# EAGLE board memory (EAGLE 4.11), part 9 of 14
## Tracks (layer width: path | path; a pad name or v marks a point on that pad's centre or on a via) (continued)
MB04  (via drill 0.61) (continued)
  Route2 0.254: v274.95,203.2 279.4,207.64 291.46,207.64 292.1,207.01 309.25,207.01 309.88,207.64 315.6,207.64 321.31,201.93 327.66,201.93 328.3,201.29 329.56,201.29 334.01,205.74 379.1,205.74 381,207.64 383.54,207.64 384.18,207.01 386.71,207.01 v387.99,208.28 | v462.28,256.54 466.73,252.09 474.35,252.09 474.35,248.28 C03.K2
  Route3 0.254: v274.95,203.2 276.23,201.93 276.23,188.59 279.4,185.42 279.4,182.88 280.67,181.61 D18.J2 | v387.99,208.28 395.61,215.9 398.14,215.9 398.14,218.44 v398.78,219.07 | B37.P2 43.18,302.26 43.81,302.9 43.81,306.71 44.45,307.34 44.45,326.39 53.98,335.92 53.98,384.81 87.63,418.47 151.76,418.47 156.84,413.39 189.23,413.39 190.5,412.12 200.03,412.12 200.66,412.75 236.85,412.75 236.85,410.21 239.4,407.67 248.28,407.67 259.71,419.1 352.43,419.1 352.43,387.99 372.75,367.67 372.75,365.76 A11.S2 | v440.06,265.43 438.15,267.34 438.15,324.49 439.42,325.75 439.42,328.3 438.15,329.56 438.15,335.92 433.07,341 v433.07,343.54
  Bottom 0.254: v439.42,170.18 434.98,170.18 434.98,163.83 433.7,162.56 D06.R2 | v474.35,224.16 466.73,216.53 437.51,216.53 v436.88,217.17 426.72,217.17 425.45,218.44 424.81,217.81 419.74,217.81 416.56,220.98 414.02,220.98 413.38,220.34 404.5,220.34 403.86,220.98 400.69,220.98 v398.78,219.07 | v462.28,256.54 460.38,258.44 453.39,258.44 452.75,259.08 448.31,259.08 441.96,265.43 v440.06,265.43 | v433.07,343.54 432.44,342.9 409.57,342.9 404.5,347.98 399.42,347.98 398.78,347.35 377.19,347.35 374.65,349.89 370.84,349.89 v370.2,349.25 | v368.3,363.86 368.94,364.49 372.75,364.49 A11.S2
MB05  (via drill 0.61)
  Top 0.254: 330.2,95.88 v331.47,97.16 | 330.2,95.88 330.2,80.64 332.11,78.74 332.11,65.41 333.38,64.13 v333.38,23.49 | v328.3,107.95 330.2,106.04 330.2,95.88 | v496.57,222.88 495.94,222.25 495.94,220.34 495.3,219.71 495.3,167 496.57,165.73 v496.57,164.47 | v502.92,137.16 504.82,135.25 v504.82,60.33 | v445.13,9.52 441.96,9.52 435.61,3.17 412.75,3.17 412.75,20.32 411.48,21.59 F08.S2 | v246.38,220.34 245.75,219.71 v245.75,208.91
  Route2 0.254: v484.5,228.6 485.77,228.6 485.77,251.46 478.15,259.08 475.62,259.08 474.98,259.72 C03.E2 | v246.38,220.34 247.65,220.34 247.65,229.23 247.01,229.87 243.21,229.87 240.03,226.69 239.4,226.69 238.76,227.33 229.87,227.33 219.07,216.53 173.35,216.53 172.09,217.81 165.74,217.81 162.56,220.98 160.02,220.98 156.21,217.17 114.94,217.17 92.71,239.39 88.9,239.39 88.9,248.92 59.69,278.13 54.61,278.13 51.44,281.31 43.18,281.31 43.18,288.29 B37.U2 | v263.52,160.66 273.69,160.66 274.32,160.02 275.59,160.02 277.5,161.92 280.67,161.92 D18.R2
  Route3 0.254: v43.18,292.1 43.18,289.56 B37.U2 | v27.3,302.26 25.4,304.17 25.4,346.08 15.88,355.6 15.88,388.62 17.14,389.89 A39.H2 | v287.65,111.12 285.75,113.03 285.75,120.02 282.57,123.19 282.57,135.25 281.31,136.53 281.31,144.78 282.57,146.05 282.57,160.02 281.31,161.29 D18.R2 | v245.75,208.91 241.3,204.47 241.3,173.99 v242.57,172.72
  Bottom 0.254: v43.18,292.1 45.09,294 45.09,297.18 36.83,297.18 33.66,300.36 29.21,300.36 v27.3,302.26 | v331.47,97.16 338.45,97.16 339.09,96.52 346.07,96.52 347.35,97.79 E13.P2 | v333.38,23.49 340.36,23.49 341,24.13 349.88,24.13 350.52,23.49 353.06,23.49 353.69,24.13 360.05,24.13 360.68,23.49 365.76,23.49 366.39,24.13 375.29,24.13 375.92,23.49 378.46,23.49 379.1,24.13 380.37,24.13 381,23.49 391.16,23.49 391.8,24.13 400.69,24.13 404.5,20.32 409.57,20.32 410.85,21.59 F08.S2 | v287.65,111.12 289.56,109.22 299.08,109.22 299.72,109.85 302.26,109.85 302.89,109.22 311.79,109.22 312.42,109.85 314.96,109.85 315.6,109.22 324.49,109.22 325.12,109.85 326.39,109.85 v328.3,107.95 | v484.5,228.6 485.77,227.33 492.12,227.33 v496.57,222.88 | v496.57,164.47 501.65,159.38 501.65,137.16 v502.92,137.16 | v504.82,60.33 504.82,27.3 494.67,27.3 476.88,9.52 v445.13,9.52 | v242.57,172.72 247.01,172.72 250.82,168.91 250.82,163.83 251.46,163.83 257.81,157.48 260.35,157.48 v263.52,160.66
MB06  (via drill 0.61)
  Top 0.254: v190.5,377.19 190.5,388.62 196.85,394.97 196.85,407.04 205.1,415.29 v252.09,415.29 | v294,414.02 298.45,414.02 298.45,392.43 297.18,391.16 A17.H2 | v238.12,217.81 v238.12,210.19 | v194.31,223.52 193.68,224.16 193.68,299.72 v191.77,301.62 | v179.71,325.75 179.71,329.56 B26.D2 | v426.72,59.05 428.62,60.96 428.62,71.12 425.45,74.29 425.45,78.74 428.62,81.91 428.62,86.36 v430.53,88.27 | v461.64,119.38 462.92,120.65 462.92,122.55 463.55,123.19 463.55,144.78 v464.82,146.05 | v459.11,209.55 459.74,210.19 459.74,217.81 460.38,218.44 460.38,221.61 v458.47,223.52
  Route2 0.254: v430.53,88.27 v461.64,119.38 | v464.82,146.05 488.95,170.18 488.95,195.58 486.41,195.58 478.79,203.2 478.79,209.55 v459.11,209.55 | v458.47,223.52 450.85,231.14 450.85,236.85 445.13,236.85 444.5,237.49 444.5,242.57 443.87,242.57 440.06,246.38 439.42,246.38 438.15,247.65 438.15,248.92 v427.36,259.72
  Route3 0.254: v338.45,53.98 336.55,52.07 336.55,46.99 335.92,46.36 335.92,44.45 332.11,44.45 F14.J2 | v190.5,377.19 186.69,373.38 186.69,371.48 184.15,368.94 184.15,357.5 177.8,351.16 177.8,335.92 178.44,335.28 178.44,331.47 179.07,330.84 B26.D2 | v277.5,209.55 277.5,207.01 279.4,205.1 279.4,199.39 280.04,198.75 280.04,194.94 280.67,194.31 D18.D2 | v191.77,301.62 187.32,306.07 187.32,324.49 v186.06,325.75 | v403.23,408.94 415.93,396.24 415.93,313.69 416.56,313.06 416.56,311.15 422.27,305.44 422.27,294.64 422.91,294 422.91,290.2 423.55,289.56 B07.U2 424.18,288.29 424.18,280.04 425.45,278.77 425.45,261.62 v427.36,259.72 | v319.4,412.12 314.32,417.2 294,417.2 v294,414.02
  Bottom 0.254: v338.45,53.98 340.36,55.88 342.26,55.88 342.9,55.25 353.06,55.25 353.69,55.88 360.05,55.88 363.22,59.05 364.49,59.05 368.3,55.25 378.46,55.25 379.1,55.88 387.99,55.88 388.62,55.25 391.16,55.25 391.8,55.88 396.88,55.88 398.14,54.61 F09.E2 398.78,54.61 399.42,55.25 403.86,55.25 407.67,59.05 416.56,59.05 417.19,58.42 426.08,58.42 v426.72,59.05 | v252.09,415.29 252.73,414.66 269.24,414.66 269.88,414.02 v294,414.02 | v277.5,209.55 276.86,208.91 265.43,208.91 263.52,210.82 238.76,210.82 v238.12,210.19 | v238.12,217.81 238.12,220.98 227.97,220.98 227.33,220.34 224.79,220.34 220.98,224.16 212.09,224.16 211.46,223.52 202.56,223.52 201.93,224.16 199.39,224.16 198.75,223.52 v194.31,223.52 | v179.71,325.75 v186.06,325.75 | v403.23,408.94 403.23,412.75 398.78,412.75 398.14,413.39 376.56,413.39 375.92,412.75 364.49,412.75 363.86,413.39 331.47,413.39 330.2,412.12 v319.4,412.12
MB07  (via drill 0.61)
  Top 0.254: C07.L2 421,245.11 421,247.65 422.91,249.56 422.91,252.73 422.27,253.36 422.27,299.72 423.55,300.99 B07.P2 | v442.6,239.39 441.32,238.12 v441.32,219.07 v441.32,207.64 | v346.07,111.76 v346.07,92.71 | v346.71,115.57 346.07,116.2 v346.07,143.51 346.07,153.67 v347.98,155.57 | v296.55,144.14 295.27,145.41 v295.27,168.28 | v284.48,168.91 281.31,172.09 281.31,173.99 D18.L2 | v390.52,190.5 v390.52,208.28
  Route2 0.254: v346.07,92.71 344.81,92.71 344.81,89.53 E13.T2 | v346.07,111.76 346.07,109.85 348.62,109.85 349.25,110.49 349.25,115.57 v346.71,115.57 | v372.75,187.32 364.49,179.07 358.77,179.07 355.6,175.89 355.6,160.66 353.06,160.66 v347.98,155.57
  Bottom 0.254: v441.32,219.07 442.6,219.07 445.77,222.25 448.94,222.25 C05.U2 | v442.6,239.39 438.79,243.2 427.99,243.2 427.36,242.57 422.27,242.57 421,243.84 C07.L2 | v346.07,143.51 345.44,144.14 318.77,144.14 317.5,142.88 314.96,142.88 313.06,144.78 297.18,144.78 v296.55,144.14 | v295.27,168.28 295.27,169.54 288.29,169.54 287.65,170.18 285.75,170.18 v284.48,168.91 | v441.32,207.64 431.17,207.64 429.89,208.91 391.16,208.91 v390.52,208.28 | v390.52,190.5 389.25,189.23 380.37,189.23 379.73,188.59 377.19,188.59 376.56,189.23 374.65,189.23 v372.75,187.32
MB08  (via drill 0.61)
  Top 0.254: v283.85,150.5 284.48,149.86 284.48,138.43 285.75,137.16 285.75,124.46 v287.65,122.55 | v290.19,83.82 290.83,83.18 290.83,73.66 292.1,72.39 292.1,59.69 293.37,58.42 296.55,58.42 296.55,54.61 F17.E2 | v361.31,231.78 365.12,227.97 v365.12,220.34 | v425.45,217.17 425.45,222.88 424.81,223.52 424.81,227.33 424.18,227.97 C07.S2 424.18,229.23 424.18,233.04 425.45,234.31 425.45,281.94 424.81,282.58 424.81,287.66 425.45,288.29 425.45,312.42 424.18,313.69 B07.K2 423.55,314.96 423.55,318.77 422.27,320.04 422.27,340.36 423.55,341.63 v423.55,356.87 | v36.2,373.38 39.37,376.56 44.45,376.56 44.45,394.34 67.31,417.2 v71.12,417.2 | v153.03,418.47 154.31,417.2 v154.31,414.66 | v393.7,416.56 400.05,410.21 v400.05,370.84
  Route2 0.254: v283.85,150.5 281.31,150.5 281.31,154.94 D18.T2 | v350.52,241.3 354.33,237.49 355.6,237.49 v361.31,231.78 | v322.58,121.92 323.21,122.55 326.39,122.55 332.74,116.2 337.82,116.2 v339.73,118.11 | v335.28,162.56 346.07,173.35 v346.07,180.97 | v341.63,224.16 343.54,222.25 344.17,222.25 345.44,223.52 353.06,223.52 353.69,224.16 355.6,224.16 v356.87,222.88
  Route3 0.254: v287.65,122.55 288.93,121.28 288.93,85.09 v290.19,83.82 | v339.73,118.11 339.73,158.11 v338.45,159.38 | v338.45,184.15 339.73,185.42 339.73,187.96 333.38,194.31 333.38,210.82 335.28,212.72 335.28,218.44 v337.82,220.98
  Bottom 0.254: v350.52,241.3 347.98,241.3 C13.M2 | v425.45,217.17 399.42,217.17 396.24,220.34 391.8,220.34 391.16,220.98 388.62,220.98 387.99,220.34 379.1,220.34 378.46,220.98 375.92,220.98 375.29,220.34 v365.12,220.34 361.95,223.52 357.5,223.52 v356.87,222.88 | v36.2,373.38 33.02,370.21 28.57,370.21 27.3,368.94 A38.R2 | v71.12,417.2 72.39,418.47 v153.03,418.47 | v154.31,414.66 154.94,415.29 161.29,415.29 161.93,415.93 191.77,415.93 193.04,417.2 252.73,417.2 254,415.93 269.24,415.93 271.78,418.47 306.07,418.47 307.98,416.56 318.77,416.56 320.68,414.66 327.66,414.66 329.56,416.56 v393.7,416.56 | v400.05,370.84 400.69,370.21 403.86,370.21 404.5,369.57 410.85,369.57 v423.55,356.87 | v287.65,122.55 288.29,121.92 299.08,121.92 299.72,122.55 302.26,122.55 302.89,121.92 311.79,121.92 312.42,122.55 314.96,122.55 315.6,121.92 v322.58,121.92 | v335.28,162.56 v338.45,159.38 | v346.07,180.97 346.07,182.25 340.36,182.25 v338.45,184.15 | v337.82,220.98 341,224.16 v341.63,224.16
MB09  (via drill 0.61)
  Top 0.254: v127.64,271.15 133.35,271.15 133.35,269.24 137.79,264.8 139.7,264.8 139.7,267.34 | 139.7,267.34 139.7,272.42 143.51,276.23 v143.51,285.12 | v353.06,324.49 352.43,323.85 v352.43,316.87 | v146.05,249.56 146.05,260.99 139.7,267.34
  Route2 0.254: v127.64,271.15 v100.33,243.84 | v143.51,285.12 144.78,283.85 147.96,283.85 149.22,285.12 152.4,285.12 153.67,283.85 179.71,283.85 189.87,294 198.12,294 201.29,297.18 210.19,297.18 210.82,296.55 213.36,296.55 214.63,297.81 217.17,297.81 B23.R2 217.81,297.81 219.07,296.55 224.16,296.55 224.79,297.18 234.31,297.18 v236.22,295.28 | v394.33,325.12 389.89,325.12 389.25,325.75 380.37,325.75 379.73,325.12 377.19,325.12 376.56,325.75 367.67,325.75 367.03,325.12 364.49,325.12 363.86,325.75 354.96,325.75 353.69,324.49 v353.06,324.49 | v352.43,316.87 347.98,312.42 339.09,312.42 338.45,313.06 330.83,313.06 v325.75,307.98 | v321.94,304.17 321.31,303.53 317.5,303.53 315.6,305.44 313.06,302.9 304.17,302.9 303.53,303.53 301.62,303.53 v297.18,299.09 | v217.81,60.96 223.52,55.25 224.16,55.25 224.79,55.88 228.6,55.88 235.59,48.9 236.85,48.9 237.49,49.53 246.38,49.53 251.46,44.45 252.09,44.45 253.37,45.72 257.81,45.72 264.16,39.37 271.14,39.37 274.32,36.2 274.95,36.2 278.76,40.01 287.65,40.01 288.29,39.37 292.74,39.37 293.37,38.73 F17.L2
  Route3 0.254: v321.94,304.17 v325.75,307.98 | v217.81,60.96 215.9,62.87 215.9,69.22 v214.63,70.48 | v164.47,69.85 152.4,81.91 152.4,125.73 139.7,138.43 139.7,163.19 146.05,169.54 v146.05,249.56
  Bottom 0.254: F17.L2 294,38.1 297.81,38.1 299.72,40.01 302.26,40.01 302.89,39.37 311.79,39.37 312.42,40.01 314.96,40.01 315.6,39.37 324.49,39.37 325.12,40.01 327.66,40.01 328.3,39.37 337.19,39.37 337.82,40.01 340.36,40.01 341,39.37 349.88,39.37 350.52,40.01 351.15,40.01 352.43,38.73 356.87,38.73 F12.L2 | v100.33,243.84 99.06,242.57 88.9,242.57 85.09,246.38 77.47,246.38 73.66,242.57 71.12,242.57 70.48,243.2 61.59,243.2 60.96,242.57 56.52,242.57 55.88,241.94 C36.M2 | v394.33,325.12 396.24,325.12 399.42,321.95 401.95,321.95 405.76,325.75 414.65,325.75 415.29,325.12 422.27,325.12 423.55,326.39 B07.E2 | v297.18,299.09 296.55,299.72 288.29,299.72 287.65,300.36 278.76,300.36 278.13,299.72 277.5,299.72 276.23,300.99 273.05,300.99 271.78,299.72 262.89,299.72 262.25,300.36 253.37,300.36 246.38,293.37 239.4,293.37 237.49,295.28 v236.22,295.28 | v214.63,70.48 193.04,70.48 191.77,69.22 181.61,69.22 180.97,69.85 v164.47,69.85
MB10  (via drill 0.61)
  Top 0.254: v74.3,238.12 76.2,240.03 76.2,276.23 78.11,278.13 v78.11,283.85 | 107.95,287.02 v102.23,287.02 | 107.95,287.02 107.95,328.3 104.78,331.47 104.78,339.09 98.42,345.44 92.08,345.44 v92.08,382.91 | v393.7,231.78 393.7,230.5 394.97,229.23 394.97,227.33 393.7,226.06 393.7,222.88 394.97,221.61 394.97,220.98 393.7,219.71 393.7,217.81 | 393.7,217.81 393.7,201.93 392.43,200.66 v392.43,198.75 | 107.95,287.02 107.95,278.13 111.12,274.96 115.57,274.96 116.2,275.59 117.47,275.59 117.47,255.91 115.57,254 115.57,253.36 v119.38,249.56 | 393.7,217.81 v393.06,217.81
  Route2 0.254: v408.31,278.13 415.93,278.13 428.62,290.83 436.25,290.83 436.25,294.64 B06.S2 | v404.5,161.92 v395.61,170.81 | v119.38,249.56 133.35,235.59 133.35,227.33 137.16,227.33 140.97,223.52 149.86,223.52 156.21,229.87 162.56,229.87 166.37,233.68 175.26,233.68 175.9,233.04 183.51,233.04 187.32,236.85 197.49,236.85 201.29,233.04 202.56,233.04 205.74,236.22 210.82,236.22 217.17,229.87 226.06,229.87 226.69,230.5 233.04,230.5 233.68,229.87 238.76,229.87 239.4,230.5 248.28,230.5 252.09,226.69 260.99,226.69 267.33,233.04 273.69,233.04 277.5,236.85 286.38,236.85 287.02,236.22 289.56,236.22 290.19,236.85 296.55,236.85 299.72,240.03 302.26,240.03 302.89,239.39 311.79,239.39 312.42,240.03 314.96,240.03 318.77,236.22 v325.75,236.22 | v328.93,217.81 329.56,217.17 359.41,217.17 363.86,221.61 365.12,221.61 370.2,216.53 391.8,216.53 v393.06,217.81
  Route3 0.254: v373.38,33.02 374.65,34.29 374.65,69.85 v377.82,73.02 | v390.52,73.66 393.06,76.2 393.06,84.45 393.7,85.09 393.7,108.58 394.97,109.85 394.97,113.66 E09.J2 395.61,114.93 395.61,116.84 396.88,118.11 396.88,140.97 403.23,147.32 403.23,159.38 403.86,160.02 403.86,161.29 v404.5,161.92 | v408.31,278.13 406.4,276.23 406.4,251.46 v404.5,249.56 | v389.25,241.3 393.7,236.85 v393.7,231.78 | v392.43,198.75 393.7,197.48 393.7,178.44 396.88,175.26 396.88,172.09 v395.61,170.81 | v325.75,236.22 327.02,234.95 327.02,227.97 328.3,226.69 328.3,225.42 327.02,224.16 327.02,219.71 v328.93,217.81
  Bottom 0.254: v74.3,238.12 72.39,236.22 71.12,236.22 70.48,236.85 61.59,236.85 60.96,236.22 56.52,236.22 55.88,235.59 C36.P2 | v78.11,283.85 84.45,283.85 88.27,287.66 99.06,287.66 99.69,287.02 v102.23,287.02 | v92.08,382.91 91.44,382.27 85.09,382.27 83.82,383.54 81.28,383.54 A34.K2 | v373.38,33.02 366.39,33.02 365.76,33.66 363.22,33.66 361.31,31.75 357.5,31.75 F12.N2 | v377.82,73.02 378.46,73.66 v390.52,73.66 | v404.5,249.56 398.14,243.2 393.7,243.2 392.43,244.47 v389.25,241.3
MB11  (via drill 0.61)
  Top 0.254: v277.5,149.86 281.31,146.05 v281.31,135.25 | v335.28,64.13 336.55,65.41 336.55,71.75 335.28,73.02 v335.28,81.91 | v331.47,103.5 330.83,104.14 330.83,106.68 330.2,107.31 330.2,112.39 331.47,113.66 E14.J2 | v181.61,271.78 184.15,271.78 184.15,306.07 185.42,307.34 v185.42,307.98 | v175.9,368.3 177.8,366.4 177.8,353.06 | v177.8,308.61 177.8,353.06 | v278.13,341.63 276.86,342.9 276.86,356.24 v277.5,356.87 | 177.8,353.06 v182.88,353.06 | v265.43,210.19 266.7,211.45 266.7,229.87 263.52,233.04 v263.52,234.95 | v207.01,271.78 204.47,274.32 204.47,276.23 203.2,277.5 201.29,277.5 201.29,275.59 v199.39,273.69
  Route2 0.254: v367.03,179.7 372.75,179.7 379.1,186.06 379.73,186.06 380.37,185.42 386.71,185.42 399.42,172.72 401.95,172.72 403.23,173.99 407.67,173.99 D08.L2 | v277.5,149.86 276.23,151.13 267.97,151.13 264.16,147.32 255.27,147.32 248.92,153.67 242.57,153.67 238.76,157.48 234.95,157.48 234.95,162.56 248.92,176.53 250.19,176.53 250.19,179.7 257.81,187.32 258.44,187.32 258.44,189.86 D20.E2 | v281.31,135.25 291.46,125.09 299.72,125.09 302.89,121.92 309.25,121.92 318.77,112.39 327.66,112.39 328.93,113.66 331.47,113.66 E14.J2 | v335.28,81.91 339.73,86.36 339.73,90.8 332.11,90.8 321.31,101.6 321.31,103.5 327.66,103.5 328.3,102.87 330.83,102.87 v331.47,103.5 | v417.83,311.15 412.12,316.87 412.12,319.41 409.57,319.41 397.51,331.47 391.16,331.47 387.35,335.28 377.19,335.28 376.56,334.65 367.67,334.65 363.86,338.46 354.96,338.46 354.33,337.82 351.79,337.82 351.15,338.46 342.26,338.46 338.45,334.65 337.19,334.65 334.01,337.82 326.39,337.82 325.75,338.46 316.87,338.46 316.23,337.82 314.96,337.82 313.69,339.09 311.79,339.09 v309.88,337.19 | v97.16,236.22 103.5,242.57 111.12,242.57 140.34,271.78 149.86,271.78 153.67,267.97 162.56,267.97 165.74,271.15 172.09,271.15 175.9,274.96 177.16,274.96 180.34,271.78 v181.61,271.78 183.51,271.78 186.69,274.96 189.23,274.96 189.87,274.32 198.75,274.32 v199.39,273.69 | v278.13,341.63 v283.85,341.63 | v277.5,356.87 276.86,357.5 273.69,357.5 266.7,350.52 212.09,350.52 209.55,353.06 v182.88,353.06 | v263.52,234.95 262.25,236.22 260.35,236.22 v259.08,237.49
  Route3 0.254: v367.03,179.7 366.39,180.34 366.39,180.97 361.95,185.42 361.95,205.74 358.77,208.91 358.77,226.69 360.05,227.97 C12.S2 | v387.35,50.16 387.35,43.82 387.99,43.18 387.99,41.27 387.35,40.64 387.35,36.2 390.52,36.2 391.8,37.46 394.97,37.46 F09.L2 | 333.38,125.09 333.38,116.2 332.11,114.93 E14.J2 | 333.38,125.09 332.11,126.36 E14.D2 | v335.28,64.13 336.55,62.87 336.55,55.88 335.28,54.61 F14.E2 | v350.52,179.07 349.25,177.8 349.25,143.51 347.35,141.6 v347.35,138.43 | v334.01,137.79 333.38,137.16 333.38,125.09 | B16.F2 306.7,324.49 307.98,325.75 307.98,335.28 v309.88,337.19 310.51,337.82 310.51,338.46 312.42,340.36 312.42,353.06 314.32,354.97 314.32,362.59 309.88,367.03 304.8,367.03 304.8,364.49 291.46,351.16 291.46,349.89 283.85,342.27 v283.85,341.63 | v263.52,191.13 263.52,196.22 262.25,197.48 262.25,198.12 263.52,199.39 263.52,208.28 v265.43,210.19 | v215.9,241.94 215.9,245.11 217.17,246.38 217.17,247.01 215.9,248.28 215.9,253.36 219.07,256.54 219.07,262.89 222.25,266.06 222.25,268.61 v220.34,270.51
  Bottom 0.254: v387.35,50.16 387.35,52.07 377.19,52.07 376.56,52.7 370.84,52.7 370.2,52.07 364.49,52.07 363.86,52.7 354.96,52.7 354.33,52.07 351.79,52.07 351.15,52.7 342.26,52.7 341.63,52.07 339.09,52.07 337.82,53.34 335.28,53.34 F14.E2 | v367.03,179.7 364.49,179.7 363.86,179.07 356.87,179.07 355.6,180.34 352.43,180.34 351.15,179.07 v350.52,179.07 | v347.35,138.43 334.64,138.43 v334.01,137.79 | v417.83,311.15 419.74,309.25 427.36,309.25 427.99,309.88 430.53,309.88 431.8,308.61 436.25,308.61 B06.M2 | v97.16,236.22 92.71,236.22 86.36,229.87 77.47,229.87 73.66,233.68 64.77,233.68 60.96,229.87 56.52,229.87 55.88,229.23 C36.S2 | v185.42,307.98 182.88,307.98 B26.M2 182.25,308.61 v177.8,308.61 | v175.9,368.3 173.99,370.21 170.81,370.21 170.18,370.84 A27.P2 | v263.52,191.13 262.89,190.5 259.08,190.5 D20.E2 | v259.08,237.49 257.18,239.39 250.19,239.39 249.56,240.03 240.66,240.03 240.03,239.39 237.49,239.39 236.85,240.03 227.97,240.03 227.33,239.39 224.79,239.39 224.16,240.03 217.81,240.03 v215.9,241.94 | v220.34,270.51 219.71,271.15 212.09,271.15 211.46,271.78 v207.01,271.78
MCA  (via drill 0.61)
  Top 0.254: v142.88,204.47 141.6,205.74 141.6,218.44 C29.V2 141.6,219.71 142.88,220.98 142.88,245.11 142.24,245.75 142.24,249.56 141.6,250.19 C29.J2
  Route2 0.254: v142.88,204.47 142.24,204.47 132.72,194.94 125.09,194.94 124.46,195.58 115.57,195.58 111.76,191.77 104.78,191.77 103.5,193.04 D32.D2
MCB  (via drill 0.61)
  Top 0.254: v101.6,207.64 101.6,176.53 102.87,175.26 D32.L2 | v131.44,208.28 132.72,209.55 132.72,219.71 136.53,223.52 v136.53,225.42 v136.53,242.57
  Bottom 0.254: v101.6,207.64 130.81,207.64 v131.44,208.28 | v136.53,225.42 140.97,225.42 C29.T2 | v136.53,242.57 130.18,242.57 128.91,243.84 C30.L2
MCC  (via drill 0.61)
  Top 0.254: v125.09,187.32 127,189.23 127,217.17 128.27,218.44 C30.V2 128.91,219.71 130.18,220.98 130.18,248.92 128.91,250.19 C30.J2
  Bottom 0.254: v125.09,187.32 123.19,185.42 121.92,185.42 121.28,186.06 112.39,186.06 111.76,185.42 107.31,185.42 106.68,184.78 D32.H2
MCD  (via drill 0.61)
  Top 0.254: v127,240.66 127,227.33 128.27,226.06 C30.T2
  Bottom 0.254: v127,240.66 127,243.2 123.19,243.2 122.56,242.57 117.47,242.57 116.2,243.84 C31.L2
MCE
  Top 0.254: C31.V2 116.2,219.71 117.47,220.98 117.47,248.92 116.2,250.19 C31.J2
MCF  (via drill 0.61)
  Top 0.254: v111.12,240.03 111.12,226.06 115.57,226.06 C31.T2
  Bottom 0.254: v111.12,240.03 107.31,243.84 103.5,243.84 C32.L2
MCG  (via drill 0.61)
  Top 0.254: C32.V2 103.5,219.71 104.78,220.98 104.78,248.92 103.5,250.19 C32.J2 | v109.22,196.85 109.22,196.22 107.95,194.94 107.95,173.35 106.68,172.09 D32.M2
  Route2 0.254: v109.22,196.85 109.22,198.12 103.5,203.84 103.5,218.44 C32.V2
MCH  (via drill 0.61)
  Top 0.254: 101.6,223.52 101.6,218.44 104.78,215.26 104.78,182.88 103.5,181.61 D32.J2 | 101.6,223.52 102.87,224.79 C32.T2 | 101.6,223.52 v101.6,246.38
  Bottom 0.254: v101.6,246.38 109.86,246.38 110.49,245.75 113.03,245.75 113.67,246.38 122.56,246.38 123.19,245.75 125.73,245.75 126.36,246.38 135.25,246.38 135.89,245.75 140.34,245.75 140.97,245.11 C29.L2
MEM_DONE  (via drill 0.61)
  Top 0.254: v111.12,27.94 111.12,24.77 104.14,17.78 98.42,17.78 98.42,45.09 92.08,51.44 92.08,136.53 90.81,137.79 v90.81,140.34
  Route2 0.254: v90.81,140.34 101.6,151.13 101.6,156.84 116.2,171.45 118.75,171.45 D31.M2
  Bottom 0.254: v111.12,27.94 106.68,27.94 F32.P2
MEMGO  (via drill 0.61)
  Top 0.254: v234.95,72.39 234.95,86.36 234.31,86.99 234.31,90.8 233.68,91.44 E22.S2 233.04,92.71 v233.04,96.52 | v352.43,71.75 352.43,99.06 354.33,100.96 356.87,100.96 E12.N2
  Route2 0.254: v140.97,99.69 v122.56,118.11
  Route3 0.254: v55.88,114.93 53.98,116.84 53.98,121.28 53.34,121.92 53.34,122.55 53.98,123.19 53.98,144.14 57.15,147.32 57.15,159.38 55.88,160.66 55.88,164.47 D36.P2
  Bottom 0.254: D36.P2 55.24,165.73 53.34,167.64 52.7,167.64 D36.N2 | v234.95,72.39 235.59,71.75 298.45,71.75 299.08,71.12 302.26,71.12 302.89,70.48 351.15,70.48 v352.43,71.75 | v55.88,114.93 61.59,109.22 70.48,109.22 74.3,113.03 80.64,113.03 87,119.38 95.89,119.38 96.52,118.74 99.06,118.74 99.69,119.38 108.58,119.38 109.22,118.74 111.76,118.74 112.39,119.38 121.28,119.38 v122.56,118.11 | v140.97,99.69 149.86,99.69 150.5,100.33 159.38,100.33 160.02,99.69 162.56,99.69 163.19,100.33 172.09,100.33 175.9,96.52 184.78,96.52 188.59,100.33 197.49,100.33 198.12,99.69 200.66,99.69 201.29,100.33 210.19,100.33 214,96.52 222.88,96.52 223.52,97.16 226.06,97.16 226.69,96.52 v233.04,96.52
N$1  (via drill 0.61)
  Top 0.254: v365.12,53.98 v365.12,157.48 v365.12,180.97
  Route2 0.254: v365.12,53.98 360.68,53.98 F12.E2
  Bottom 0.254: v365.12,157.48 365.12,163.19 371.48,163.19 372.75,164.47 D11.P2 | v365.12,180.97 369.57,180.97 D11.J2
N$2  (via drill 0.61)
  Top 0.254: v452.75,212.72 450.85,214.63 v450.85,228.6
  Route3 0.254: v500.38,180.97 498.48,182.88 498.48,202.56 v496.57,204.47 | v450.85,228.6 452.12,229.87 449.58,232.41 v449.58,233.04
  Bottom 0.254: v500.38,180.97 502.29,179.07 504.82,179.07 504.82,113.66 490.86,99.69 488.31,99.69 487.68,99.06 E02.P2 | v496.57,204.47 496.57,210.82 491.49,210.82 490.86,211.45 467.36,211.45 465.45,213.36 453.39,213.36 v452.75,212.72 | v449.58,233.04 442.6,233.04 438.15,237.49 433.7,237.49 C06.N2
N$3  (via drill 0.61)
  Top 0.254: v368.3,184.15 368.3,151.13 369.57,149.86 D11.V2 370.2,148.59 v370.2,135.25
  Route2 0.254: v376.56,28.58 384.18,36.2 391.16,36.2 v396.24,41.27
  Route3 0.254: F08.V2 407.67,13.34 403.23,13.34 403.23,34.29 v396.24,41.27 395.61,41.91 395.61,43.82 F09.J2 395.61,45.09 396.88,46.36 396.88,67.31 398.14,68.58 398.14,71.12 v396.24,73.02 | v360.68,24.77 360.68,22.86 F12.S2 | v376.56,135.25 377.82,133.99 377.82,93.34 374.65,90.17 374.65,77.47 v377.82,74.29
  Bottom 0.254: v368.3,184.15 372.75,184.15 D11.H2 | v360.68,24.77 363.22,27.3 365.76,27.3 366.39,26.67 374.01,26.67 375.92,28.58 v376.56,28.58 | v370.2,135.25 v376.56,135.25 | v377.82,74.29 378.46,74.93 394.33,74.93 v396.24,73.02
N$4  (via drill 0.61)
  Top 0.254: 358.77,153.67 358.77,187.96 360.05,189.23 360.05,189.86 D12.E2 | 358.77,153.67 358.77,53.34 360.05,52.07 360.05,48.26 F12.H2 | v359.41,153.67 358.77,153.67
  Bottom 0.254: v359.41,153.67 363.86,153.67 365.12,154.94 369.57,154.94 D11.T2
N$5  (via drill 0.61)
  Top 0.254: 409.57,156.84 409.57,151.13 408.31,149.86 D08.V2 | 409.57,156.84 410.85,158.11 D08.S2 | 409.57,156.84 409.57,166.37 408.31,167.64 D08.N2 408.31,168.91 408.94,169.54 408.94,173.35 410.85,175.26 410.85,177.16 D08.K2 410.85,178.44 409.57,179.7 409.57,185.42 408.31,186.69 D08.F2 | D07.K2 423.55,178.44 423.55,182.25 421,184.78 421,186.69 D07.F2 | v312.42,327.03 314.32,325.12 v314.32,276.86 | v403.23,187.32 v403.23,273.69
  Route2 0.254: v312.42,327.03 309.88,327.03 B16.E2
  Bottom 0.254: v314.32,276.86 365.12,276.86 365.76,276.23 379.73,276.23 381.63,274.32 391.16,274.32 391.8,274.96 401.95,274.96 v403.23,273.69 | v403.23,187.32 407.67,187.32 D08.F2 | D07.K2 423.55,178.44 422.91,179.07 418.46,179.07 417.83,179.7 416.56,179.7 415.29,178.44 411.48,178.44 D08.K2
N$6  (via drill 0.61)
  Top 0.254: 361.95,163.19 361.95,43.18 360.68,41.91 F12.K2 | 361.95,163.19 360.68,164.47 D12.P2 | v360.05,180.34 361.95,178.44 361.95,163.19
  Bottom 0.254: v360.05,180.34 357.5,180.34 D12.J2
N$7  (via drill 0.61)
  Top 0.254: v282.57,144.78 282.57,163.19 283.85,164.47 D18.P2 | v354.96,145.41 355.6,146.05 355.6,153.67 354.33,154.94 v354.33,155.57 | v352.43,172.09 v352.43,190.5
  Route2 0.254: v352.43,190.5 347.98,190.5 D13.E2
  Route3 0.254: v352.43,172.09 352.43,162.56 356.87,158.11 356.87,156.21 D12.T2
  Bottom 0.254: v282.57,144.78 291.46,144.78 292.1,145.41 v354.96,145.41 | v354.33,155.57 356.87,155.57 D12.T2
N$8
  Top 0.254: D13.P2 347.35,165.73 346.71,166.37 346.71,170.18 346.07,170.81 346.07,179.07 344.81,180.34 D13.J2
  Bottom 0.254: D18.K2 284.48,178.44 285.12,179.07 289.56,179.07 290.19,179.7 299.08,179.7 302.89,175.89 304.17,175.89 307.34,179.07 313.69,179.07 314.96,180.34 317.5,180.34 318.77,179.07 326.39,179.07 327.66,180.34 330.2,180.34 331.47,179.07 339.09,179.07 340.36,180.34 344.17,180.34 D13.J2
N$9
  Route3 0.254: D14.E2 335.28,189.86 336.55,188.59 336.55,180.34 339.73,177.16 339.73,163.19 344.17,158.75 344.17,156.21 D13.T2
  Bottom 0.254: D18.S2 284.48,158.11 285.12,157.48 289.56,157.48 290.19,156.84 299.08,156.84 299.72,157.48 302.26,157.48 302.89,156.84 311.79,156.84 312.42,157.48 314.96,157.48 315.6,156.84 324.49,156.84 325.12,157.48 327.66,157.48 328.3,156.84 337.19,156.84 337.82,157.48 339.09,157.48 341,155.57 344.17,155.57 D13.T2
N$10  (via drill 0.61)
  Top 0.254: v325.75,166.37 327.66,166.37 327.66,167 328.3,167.64 328.3,169.54 327.02,170.81 v327.02,180.97
  Route3 0.254: v311.15,186.69 v313.69,184.15
  Bottom 0.254: v311.15,186.69 309.25,188.59 302.89,188.59 302.26,189.23 299.72,189.23 299.08,188.59 290.19,188.59 289.56,189.23 285.12,189.23 284.48,189.86 D18.E2 | v313.69,184.15 315.6,182.25 324.49,182.25 325.12,182.88 327.02,182.88 328.3,181.61 | 328.3,181.61 328.93,180.97 331.47,180.97 D14.J2 | v325.75,166.37 327.02,166.37 327.66,167 333.38,167 334.64,165.73 D14.P2 | v327.02,180.97 327.66,181.61 328.3,181.61
N$11  (via drill 0.61)
  Top 0.254: v313.69,177.16 314.32,177.8 314.32,180.34 321.94,187.96 321.94,189.86 D15.E2 | v331.47,160.02 331.47,156.21 D14.T2
  Route2 0.254: v331.47,160.02 327.02,164.47 v327.02,167.64
  Route3 0.254: v327.02,167.64 327.02,179.7 328.3,180.97 328.3,181.61 322.58,187.32 322.58,189.86 D15.E2
  Bottom 0.254: v313.69,177.16 313.06,176.53 306.07,176.53 302.26,172.72 299.72,172.72 299.08,173.35 290.19,173.35 288.93,172.09 284.48,172.09 D18.M2
N$12  (via drill 0.61)
  Top 0.254: v288.93,152.4 v288.93,161.92 | D15.J2 319.4,180.34 320.68,179.07 320.68,167 321.94,165.73 D15.P2
  Bottom 0.254: v288.93,152.4 284.48,152.4 D18.U2 | v288.93,161.92 290.19,163.19 299.08,163.19 299.72,163.83 302.26,163.83 302.89,163.19 311.79,163.19 312.42,163.83 314.96,163.83 315.6,163.19 320.68,163.19 321.94,164.47 D15.P2
N$13  (via drill 0.61)
  Top 0.254: v318.77,166.37 320.68,164.47 320.68,151.13 319.4,149.86 D15.V2 | v317.5,173.99 317.5,181.61 319.4,183.51 321.94,183.51 D15.H2 | v357.5,22.86 352.43,27.94 352.43,70.48 353.69,71.75 v353.69,76.2 | v314.32,76.83 v314.32,148.59
  Route3 0.254: v318.77,166.37 317.5,167.64 v317.5,173.99 | v357.5,22.86 362.58,17.78 362.58,17.14 363.86,17.14 368.3,21.59 372.75,21.59 F11.S2
  Bottom 0.254: v353.69,76.2 345.44,76.2 344.17,77.47 321.31,77.47 320.68,76.83 v314.32,76.83 | v314.32,148.59 318.77,148.59 D15.V2
N$14  (via drill 0.61)
  Top 0.254: v373.38,74.29 373.38,73.02 374.65,71.75 374.65,30.48 373.38,29.21 F11.P2 | v343.54,74.29 342.9,74.93 v342.9,156.84 | v317.5,160.02 317.5,172.72 318.77,173.99 D15.L2
  Bottom 0.254: v373.38,74.29 372.75,73.66 348.62,73.66 347.98,74.29 v343.54,74.29 | v342.9,156.84 341,156.84 339.73,158.11 335.28,158.11 D14.S2 334.64,158.75 331.47,158.75 329.56,160.66 328.3,160.66 327.66,160.02 v317.5,160.02
N$15  (via drill 0.61)
  Top 0.254: v287.02,67.31 287.65,67.94 287.65,74.29 288.93,75.56 v288.93,146.05
  Route3 0.254: v287.02,67.31 287.02,66.04 282.57,61.59 282.57,55.88 283.85,54.61 F18.E2 | v331.47,183.51 330.2,182.25 330.2,151.13 331.47,149.86 D14.V2
  Bottom 0.254: v288.93,146.05 325.75,146.05 327.02,147.32 327.02,149.22 331.47,149.22 D14.V2 | v331.47,183.51 334.64,183.51 D14.H2
N$16  (via drill 0.61)
  Top 0.254: v371.48,143.51 371.48,40.64 372.11,40.01 372.11,36.2 372.75,35.56 F11.M2 | v352.43,143.51 v352.43,158.11 | v342.26,173.35 342.9,172.72 v342.9,158.75
  Bottom 0.254: v371.48,143.51 370.84,142.88 353.06,142.88 v352.43,143.51 | v352.43,158.11 347.98,158.11 D13.S2 347.35,158.75 v342.9,158.75 | v342.26,173.35 341,173.35 340.36,172.72 333.38,172.72 332.11,173.99 D14.L2
N$17  (via drill 0.61)
  Top 0.254: v379.73,36.83 381,38.1 381,140.97 379.73,142.24 v379.73,144.78 | v317.5,144.14 317.5,153.03 318.77,154.31 318.77,154.94 D15.T2 | v307.98,180.34 307.98,188.59 309.25,189.86 D16.E2
  Route2 0.254: v307.98,180.34 301.62,173.99 301.62,167 304.8,167 315.6,156.21 318.77,156.21 D15.T2
  Bottom 0.254: v379.73,36.83 379.1,36.83 378.46,36.2 373.38,36.2 372.75,36.83 366.39,36.83 365.76,36.2 361.31,36.2 360.68,35.56 F12.M2 | v379.73,144.78 361.31,144.78 360.05,143.51 353.69,143.51 352.43,144.78 318.13,144.78 v317.5,144.14
N$18  (via drill 0.61)
  Top 0.254: v370.2,16.51 368.3,18.41 v368.3,138.43 | v327.02,139.06 v327.02,158.75
  Route2 0.254: v370.2,16.51 372.75,16.51 F11.U2 | D16.L2 306.7,173.99 306.7,169.54 307.34,169.54 315.6,161.29 317.5,161.29 319.4,159.38 321.94,159.38 D15.S2
  Bottom 0.254: v368.3,138.43 351.79,138.43 350.52,139.7 327.66,139.7 v327.02,139.06 | v327.02,158.75 322.58,158.75 D15.S2
N$19  (via drill 0.61)
  Top 0.254: v356.24,79.38 356.24,65.41 355.6,64.77 355.6,31.12 356.87,29.84 356.87,29.21 360.05,29.21 F12.P2 | v311.15,79.38 311.15,163.19 309.88,164.47 D16.P2 309.25,165.73 307.98,167 307.98,179.07 306.7,180.34 D16.J2
  Bottom 0.254: v356.24,79.38 v311.15,79.38
N$20  (via drill 0.61)
  Top 0.254: 346.07,156.84 346.07,169.54 343.54,172.09 343.54,173.35 342.9,173.99 342.9,181.61 344.81,183.51 347.35,183.51 D13.H2 | 346.07,156.84 346.07,154.94 345.44,154.31 345.44,150.5 344.81,149.86 D13.V2 | 346.07,156.84 v347.98,156.84
  Route3 0.254: v363.86,157.48 365.12,156.21 365.12,144.78 371.48,138.43 371.48,46.99 372.11,46.36 372.11,42.55 372.75,41.91 F11.K2
  Bottom 0.254: v363.86,157.48 354.96,157.48 354.33,156.84 351.79,156.84 351.15,157.48 348.62,157.48 v347.98,156.84
N$21  (via drill 0.61)
  Top 0.254: v350.52,172.72 352.43,170.81 v352.43,161.29 | v372.75,51.44 372.75,48.26 F11.H2
  Route2 0.254: v370.2,53.98 v372.75,51.44
  Route3 0.254: v370.2,53.98 368.94,55.25 368.94,55.88 368.3,56.52 368.3,137.16 361.95,143.51 361.95,156.84 360.68,158.11 D12.S2
  Bottom 0.254: v350.52,172.72 346.07,172.72 344.81,173.99 D13.L2 | v352.43,161.29 353.06,160.66 358.77,160.66 360.05,159.38 D12.S2
N$22  (via drill 0.61)
  Top 0.254: v355.6,181.61 355.6,154.94 356.24,154.31 356.24,150.5 356.87,149.86 D12.V2 | v372.75,56.52 372.75,54.61 F11.E2
  Route2 0.254: v372.75,56.52 372.11,55.88 368.94,55.88 368.3,56.52 368.3,62.23 v367.03,62.23
  Route3 0.254: v367.03,62.23 365.76,63.5 365.76,65.41 365.12,66.04 365.12,139.06 361.31,142.88 361.31,144.78 357.5,148.59 D12.V2
  Bottom 0.254: v355.6,181.61 357.5,183.51 360.05,183.51 D12.H2
N$23  (via drill 0.61)
  Top 0.254: v354.33,31.75 354.33,30.48 358.77,26.03 358.77,17.78 360.05,16.51 F12.U2
  Route2 0.254: v369.57,157.48 368.3,157.48 368.3,160.02 358.77,169.54 357.5,169.54 357.5,173.99 D12.L2
  Route3 0.254: v354.33,31.75 355.6,33.02 355.6,74.93 357.5,76.83 357.5,80.01 355.6,81.91 355.6,93.34 354.96,93.98 354.96,96.52 356.87,98.42 356.87,99.69 355.6,100.96 355.6,102.87 356.24,103.5 356.24,104.14 356.87,104.77 356.87,106.04 352.43,110.49 352.43,125.73 353.69,127 353.69,128.27 352.43,129.54 352.43,142.24 353.69,143.51 353.69,148.59 358.14,153.03 358.14,154.31 358.77,154.94 358.77,172.72 357.5,173.99 D12.L2
  Bottom 0.254: v369.57,157.48 368.3,158.75 368.3,160.02 372.11,160.02 372.75,159.38 D11.S2
N$24  (via drill 0.61)
  Top 0.254: v337.82,111.76 339.73,109.85 339.73,76.83 342.9,73.66 342.9,48.9 346.07,45.72 346.07,36.83 347.35,35.56 F13.M2 | v308.61,116.2 307.98,116.84 307.98,140.34 306.7,141.6 306.7,148.59 D16.V2 306.07,149.86 304.8,151.13 304.8,181.61 v306.7,183.51
  Route2 0.254: v306.7,183.51 309.25,183.51 D16.H2
  Bottom 0.254: v337.82,111.76 334.01,115.57 326.39,115.57 325.75,116.2 316.87,116.2 316.23,115.57 313.69,115.57 313.06,116.2 v308.61,116.2
N$25
  Route3 0.254: D16.T2 306.07,156.21 304.8,157.48 304.8,183.51 307.98,186.69 307.98,217.17 311.15,220.34 311.15,255.27 307.98,258.44 307.98,270.51 302.26,276.23 302.26,277.5 304.8,280.04 304.8,313.69 309.25,318.14 309.25,320.04 B16.H2
N$26  (via drill 0.61)
  Top 0.254: v319.4,138.43 315.6,142.24 315.6,150.5 314.32,151.76 v314.32,158.75
  Route3 0.254: v332.11,47.62 330.83,48.9 330.83,49.53 327.02,53.34 327.02,116.2 323.85,119.38 v323.85,139.06
  Bottom 0.254: v332.11,47.62 333.38,46.36 338.45,46.36 339.09,45.72 341.63,45.72 343.54,47.62 347.35,47.62 F13.H2 | v323.85,139.06 320.04,139.06 v319.4,138.43 | v314.32,158.75 309.88,158.75 D16.S2
N$27  (via drill 0.61)
  Route3 0.254: v481.33,113.03 476.25,118.11 476.25,134.62 477.52,135.89 v477.52,144.78 | v446.4,151.76 444.5,153.67 444.5,162.56 445.77,163.83 445.77,166.37 443.87,168.28 443.87,170.18 444.5,170.81 444.5,217.17 441.32,220.34 441.32,226.69 438.15,229.87 438.15,241.94 433.7,246.38 433.7,250.19 C06.J2
  Bottom 0.254: v481.33,113.03 485.77,113.03 487.05,111.76 E02.K2 | v477.52,144.78 453.39,144.78 v446.4,151.76
N$28  (via drill 0.61)
  Top 0.254: v471.81,182.88 469.9,184.78 469.9,215.26 471.17,216.53 471.17,218.44 C03.V2
  Route3 0.254: v473.71,135.25 472.44,136.53 472.44,147.95 473.07,148.59 473.07,181.61 v471.81,182.88
  Bottom 0.254: v473.71,135.25 480.69,128.27 487.05,128.27 487.05,124.46 E02.E2
N$29  (via drill 0.61)
  Top 0.254: v484.5,179.07 484.5,178.44 482.6,176.53 482.6,157.48 483.87,156.21 D02.T2 | v487.68,179.7 487.05,180.34 487.05,182.25 485.77,183.51 v485.77,224.79 | v471.81,227.33 471.81,231.14 C03.R2
  Route2 0.254: v484.5,179.07 485.14,179.7 v487.68,179.7
  Bottom 0.254: v485.77,224.79 485.77,226.69 478.79,226.69 478.15,227.33 v471.81,227.33
N$30  (via drill 0.61)
  Route3 0.254: v476.25,244.47 476.25,229.23 480.69,224.79 480.69,224.16 479.43,222.88 479.43,210.82 473.07,204.47 473.07,182.88 478.79,177.16 v478.79,175.89
  Bottom 0.254: v476.25,244.47 471.81,244.47 C03.L2 | v478.79,175.89 483.87,170.81 483.87,168.91 D02.N2
N$31  (via drill 0.61)
  Top 0.254: v501.65,186.06 501.65,243.2 v499.75,245.11
  Route3 0.254: v484.5,184.78 484.5,181.61 D02.J2
  Bottom 0.254: v484.5,184.78 485.14,185.42 492.76,185.42 493.39,186.06 v501.65,186.06 | v499.75,245.11 499.11,245.75 491.49,245.75 490.86,246.38 484.5,246.38 478.79,252.09 478.79,255.27 477.52,255.27 476.25,256.54 471.81,256.54 C03.F2
N$32  (via drill 0.61)
  Top 0.254: v488.31,219.71 488.95,220.34 488.95,247.01 495.3,253.36 v495.3,273.05 | v421,280.04 421,285.12 B07.V2
  Bottom 0.254: v488.31,219.71 484.5,219.71 C02.V2 | v495.3,273.05 495.3,277.5 477.52,277.5 474.98,280.04 v421,280.04
N$33  (via drill 0.61)
  Top 0.254: v474.98,243.2 473.71,244.47 473.71,246.38 473.07,247.01 v473.07,278.77
  Route3 0.254: v424.18,278.77 422.27,280.67 422.27,293.37 421,294.64 421,297.81 B07.R2
  Bottom 0.254: v474.98,243.2 481.33,236.85 483.87,236.85 483.87,232.41 C02.R2 | v473.07,278.77 472.44,279.4 424.81,279.4 v424.18,278.77
N$34  (via drill 0.61)
  Route2 0.254: v465.45,278.13 463.55,278.13 463.55,269.24 483.24,249.56 483.87,249.56 483.87,245.11 C02.L2
  Route3 0.254: v427.36,278.13 425.45,280.04 425.45,304.17 421,308.61 421,310.52 B07.L2
  Bottom 0.254: v465.45,278.13 464.82,278.77 427.99,278.77 v427.36,278.13
N$35  (via drill 0.61)
  Top 0.254: v433.07,277.5 431.8,278.77 431.8,302.9 v429.89,304.8 | v424.18,310.52 422.27,312.42 422.27,318.77 421,320.04 421,323.22 B07.F2
  Route2 0.254: v471.81,271.78 466.73,276.86 v465.45,276.86 | v429.89,304.8 v424.18,310.52
  Bottom 0.254: v471.81,271.78 481.33,262.25 483.87,262.25 483.87,257.81 C02.F2 | v465.45,276.86 464.82,277.5 v433.07,277.5
N$36
  Bottom 0.254: B02.U2 487.05,288.29 487.05,283.21 444.5,283.21 436.25,291.47 433.7,291.47 B06.T2
N$37
  Bottom 0.254: B02.P2 487.05,302.26 485.77,303.53 478.79,303.53 478.15,302.9 469.26,302.9 465.45,306.71 462.92,306.71 459.74,303.53 453.39,303.53 452.75,302.9 443.87,302.9 443.23,303.53 440.69,303.53 440.06,302.9 434.98,302.9 433.7,304.17 B06.N2
N$38  (via drill 0.61)
  Top 0.254: B16.T2 306.7,292.74 307.34,293.37 307.34,297.18 307.98,297.81 307.98,307.34 306.7,308.61 306.7,310.52 B16.L2 | D07.S2 423.55,159.38 422.27,160.66 422.27,163.19 421,164.47 421,167.64 D07.N2 421,168.91 v421,172.72
  Route2 0.254: v316.87,317.5 318.77,315.6 327.66,315.6 328.3,316.23 337.19,316.23 337.82,315.6 338.45,315.6 v341.63,318.77 | v346.71,341 347.98,342.27 360.68,342.27 361.95,341 365.76,341 366.39,341.63 372.75,341.63 373.38,341 378.46,341 379.1,341.63 394.33,341.63 401.32,334.65 403.86,334.65 404.5,335.28 405.13,335.28 434.98,305.44 434.98,299.09 v436.25,299.09 | v459.11,288.93 v449.58,298.45 | v463.55,194.31 461.64,192.41 453.39,192.41 449.58,188.59 445.13,188.59 440.69,184.15 440.06,184.15 428.62,172.72 v421,172.72
  Route3 0.254: v311.15,311.15 311.15,311.79 v316.87,317.5 | v341.63,318.77 346.07,323.22 346.07,340.36 v346.71,341 | v459.11,288.93 463.55,284.48 463.55,222.88 466.73,219.71 466.73,197.48 v463.55,194.31
  Bottom 0.254: D10.L2 382.9,173.99 382.9,170.18 391.16,170.18 391.8,169.54 398.14,169.54 401.32,166.37 403.86,166.37 404.5,167 413.38,167 414.02,166.37 415.29,166.37 416.56,167.64 420.37,167.64 D07.N2 | v311.15,311.15 306.7,311.15 B16.L2 | v436.25,299.09 438.79,296.55 441.96,296.55 442.6,297.18 448.31,297.18 v449.58,298.45
N$39  (via drill 0.61)
  Top 0.254: v346.71,191.77 342.9,191.77 342.9,210.82 341.63,212.09 v341.63,219.07 | v328.93,249.56 329.56,250.19 329.56,252.73 330.2,253.36 330.2,262.89 327.02,266.06 327.02,273.05 323.85,276.23 v323.85,285.75 | v306.7,301.62 306.7,304.17 B16.N2
  Route2 0.254: v341.63,231.78 341.63,233.04 346.07,237.49 346.07,243.2 339.73,243.2 337.82,241.3 337.19,241.3 v328.93,249.56 | v322.58,297.81 320.68,299.72 313.69,299.72 313.06,300.36 307.98,300.36 v306.7,301.62
  Route3 0.254: v341.63,219.07 339.73,220.98 339.73,229.87 v341.63,231.78 | v323.85,285.75 323.85,296.55 v322.58,297.81
  Bottom 0.254: v346.71,191.77 351.15,191.77 351.79,192.41 354.33,192.41 354.96,191.77 363.86,191.77 364.49,192.41 371.48,192.41 372.75,191.13 D11.E2
N$40  (via drill 0.61)
  Top 0.254: v429.89,161.92 431.8,163.83 v431.8,177.16
  Route2 0.254: v391.8,298.45 389.89,300.36 386.71,300.36 383.54,297.18 379.1,297.18 378.46,296.55 375.92,296.55 375.29,297.18 366.39,297.18 365.76,296.55 362.58,296.55 359.41,299.72 353.06,299.72 349.25,303.53 341,303.53 340.36,302.9 329.56,302.9 323.21,309.25 318.77,309.25 312.42,315.6 307.98,315.6 306.7,316.87 B16.J2
  Route3 0.254: v391.8,298.45 390.52,297.18 390.52,281.31 389.25,280.04 391.16,278.13 393.7,278.13 393.7,246.38 392.43,245.11 v392.43,243.2 | v417.83,243.2 419.1,241.94 419.1,212.09 417.83,210.82 v417.83,206.38 | v426.72,205.74 428.62,203.84 428.62,202.56 431.8,199.39 v431.8,177.16
  Bottom 0.254: v429.89,161.92 427.99,160.02 426.72,160.02 426.08,160.66 417.19,160.66 416.56,160.02 414.02,160.02 413.38,160.66 404.5,160.66 403.86,160.02 399.42,160.02 398.78,159.38 D09.S2 | v431.8,177.16 436.25,177.16 D06.K2 | v392.43,243.2 393.06,242.57 403.86,242.57 404.5,243.2 413.38,243.2 414.02,242.57 416.56,242.57 417.19,243.2 v417.83,243.2 | v417.83,206.38 418.46,205.74 v426.72,205.74
N$41  (via drill 0.61)
  Route3 0.254: v424.18,109.22 425.45,107.95 425.45,100.96 431.8,94.61 431.8,78.74 433.07,77.47 433.07,65.41 431.8,64.13 431.8,50.16 v456.56,25.4
  Bottom 0.254: v424.18,109.22 421,109.22 421,113.66 E07.J2 | v456.56,25.4 461.01,20.95 467.36,20.95 468,20.32 476.88,20.32 481.33,24.77 483.87,24.77 F02.R2
N$42  (via drill 0.61)
  Top 0.254: 433.7,147.32 434.98,147.32 434.98,166.37 433.7,167.64 D06.N2 | 433.7,147.32 v433.07,147.32 | 433.7,147.32 433.7,144.14 434.98,142.88 434.98,88.27 434.34,87.63 434.34,83.82 433.7,83.18 E06.V2
  Route2 0.254: v433.07,147.32 422.27,147.32 421,148.59 D07.V2
N$43  (via drill 0.61)
  Top 0.254: v139.7,132.72 139.7,122.55 140.97,121.28 E29.F2 | v116.2,137.16 115.57,137.79 v115.57,146.05
  Bottom 0.254: v139.7,132.72 137.16,135.25 126.36,135.25 125.73,134.62 123.19,134.62 122.56,135.25 118.11,135.25 v116.2,137.16 | v115.57,146.05 80.64,146.05 79.38,147.32 78.74,147.32 78.11,146.69 57.78,146.69 56.52,147.95 48.26,147.95 46.35,146.05 17.14,146.05 14.61,148.59 D39.V2
N$44  (via drill 0.61)
  Top 0.254: v487.05,102.87 488.95,100.96 488.95,71.75 482.6,65.41 482.6,20.95 483.87,19.69 F02.T2
  Bottom 0.254: v487.05,102.87 480.69,102.87 480.06,103.5 477.52,103.5 476.88,102.87 468,102.87 464.19,106.68 455.3,106.68 451.49,102.87 442.6,102.87 438.79,106.68 429.89,106.68 429.26,106.04 422.27,106.04 421,107.31 E07.L2
N$45
  Bottom 0.254: D30.T2 128.91,154.94 130.81,153.03 131.44,153.03 D30.U2
N$46  (via drill 0.61)
  Top 0.254: v441.32,43.82 441.32,13.34 445.77,13.34 F05.V2
  Bottom 0.254: v441.32,43.82 444.5,46.99 448.94,46.99 F05.H2
N$47  (via drill 0.61)
  Top 0.254: F05.P2 448.94,29.21 447.68,30.48 447.68,41.91 446.4,43.18 446.4,43.82 F05.J2 | v479.43,73.66 479.43,83.18 474.98,87.63 474.98,91.44 E03.S2
  Route2 0.254: v479.43,73.66 450.85,45.09 446.4,45.09 F05.J2
N$48  (via drill 0.61)
  Top 0.254: v230.5,358.78 228.6,356.87 v228.6,318.77 | v224.16,314.33 219.07,309.25 219.07,294 220.34,292.74 220.34,289.56 B23.U2
  Route2 0.254: v224.16,314.33 v228.6,318.77
  Route3 0.254: v246.38,393.06 241.3,387.99 241.3,369.57 v230.5,358.78
  Bottom 0.254: B23.V2 217.81,286.39 219.71,288.29 220.34,288.29 B23.U2 | v246.38,393.06 248.92,395.61 249.56,395.61 250.19,394.97 257.18,394.97 258.44,396.24 A20.E2
N$49
  Bottom 0.254: C25.E2 195.58,260.99 200.03,260.99 201.93,262.89 204.47,262.89 C24.D2
N$50  (via drill 0.61)
  Top 0.254: v233.68,231.14 233.68,229.23 C22.S2
  Route2 0.254: v233.68,231.14 236.22,233.68 238.76,233.68 240.03,232.41 242.57,232.41 C21.R2
N$51
  Bottom 0.254: C22.P2 233.68,235.59 234.31,236.22 238.12,236.22 240.03,238.12 242.57,238.12 C21.N2
N$52
  Bottom 0.254: C22.M2 233.68,241.94 234.31,242.57 238.76,242.57 240.03,243.84 242.57,243.84 C21.L2
N$53
  Bottom 0.254: B26.V2 179.71,286.39 180.97,287.66 187.96,287.66 188.59,287.02 197.49,287.02 198.12,287.66 200.66,287.66 201.29,287.02 210.19,287.02 214.63,291.47 217.17,291.47 B23.T2
N$54  (via drill 0.61)
  Top 0.254: v155.57,344.17 155.57,381.64 154.31,382.91 154.31,386.72 A28.J2 | v298.45,342.9 v298.45,70.48 | v399.42,67.94 400.05,67.31 v400.05,33.66
  Bottom 0.254: v155.57,344.17 164.47,344.17 165.74,342.9 218.44,342.9 219.71,344.17 220.34,344.17 222.25,342.27 266.06,342.27 266.7,342.9 v298.45,342.9 | v298.45,70.48 301.62,70.48 302.26,69.85 368.94,69.85 370.2,68.58 396.24,68.58 396.88,67.94 v399.42,67.94 | v400.05,33.66 402.59,33.66 403.86,32.38 407.67,32.38 F08.N2 408.31,31.12 408.94,31.12 410.85,29.21 F08.P2
N$55
  Bottom 0.254: C22.K2 233.68,248.28 234.31,248.92 236.85,248.92 238.12,250.19 242.57,250.19 C21.J2
N$56  (via drill 0.61)
  Route2 0.254: v238.12,254.63 240.03,256.54 242.57,256.54 C21.F2
  Bottom 0.254: v238.12,254.63 233.68,254.63 C22.H2
N$57
  Bottom 0.254: C22.E2 233.68,260.99 234.31,261.62 238.76,261.62 240.03,262.89 242.57,262.89 C21.D2
N$58  (via drill 0.61)
  Route3 0.254: v198.12,254 200.03,252.09 202.56,252.09 202.56,252.73 203.2,253.36 203.2,255.27 204.47,256.54 C24.F2
  Bottom 0.254: v198.12,254 195.58,254 C25.H2
N$59
  Bottom 0.254: C25.K2 195.58,248.28 196.22,248.92 199.39,248.92 200.66,250.19 204.47,250.19 C24.J2
N$60  (via drill 0.61)
  Top 0.254: v200.03,241.3 v200.03,244.47
  Bottom 0.254: v200.03,241.3 195.58,241.3 C25.M2 | v200.03,244.47 204.47,244.47 C24.L2
N$61
  Bottom 0.254: C25.P2 195.58,235.59 196.22,236.22 200.66,236.22 201.93,237.49 204.47,237.49 C24.N2
N$62
  Route2 0.254: C25.S2 195.58,229.23 196.22,229.87 200.66,229.87 201.93,231.14 204.47,231.14 C24.R2
N$63  (via drill 0.61)
  Top 0.254: v181.61,227.33 180.97,227.97 180.97,257.81 v179.07,259.72
  Bottom 0.254: v181.61,227.33 186.06,227.33 186.69,226.69 189.23,226.69 189.87,227.33 198.75,227.33 200.66,225.42 204.47,225.42 C24.T2 | v179.07,259.72 176.53,262.25 173.99,262.25 172.72,260.99 170.18,260.99 C27.E2
N$64  (via drill 0.61)
  Top 0.254: v168.28,344.17 168.28,294 167,292.74 B27.T2 | v245.75,344.17 247.65,346.08 247.65,369.57 246.38,370.84 A21.P2
  Bottom 0.254: v168.28,344.17 168.91,343.54 217.81,343.54 219.07,344.81 220.98,344.81 222.88,342.9 244.47,342.9 v245.75,344.17 | A21.N2 243.21,374.02 245.11,372.11 245.75,372.11 A21.P2
N$65  (via drill 0.61)
  Top 0.254: v230.5,265.43 228.6,267.34 228.6,276.23 227.33,277.5 v227.33,285.75
  Route2 0.254: v407.67,261.62 407.04,262.25 402.59,262.25 398.78,258.44 389.89,258.44 389.25,259.08 380.37,259.08 376.56,255.27 367.67,255.27 367.03,255.91 364.49,255.91 363.86,255.27 354.96,255.27 354.33,255.91 351.79,255.91 351.15,255.27 342.26,255.27 338.45,259.08 330.83,259.08 327.02,255.27 316.87,255.27 313.06,259.08 304.17,259.08 303.53,258.44 300.99,258.44 297.81,261.62 291.46,261.62 290.83,262.25 288.29,262.25 287.65,261.62 280.04,261.62 279.4,262.25 275.59,262.25 274.95,261.62 270.51,261.62 269.88,262.25 262.89,262.25 262.25,261.62 v255.91,261.62
  Route3 0.254: v227.33,285.75 225.43,287.66 225.43,292.74 220.98,297.18 220.98,300.99 B23.P2
  Bottom 0.254: B27.R2 167,299.09 168.28,300.36 172.72,300.36 175.9,303.53 184.78,303.53 185.42,302.9 187.96,302.9 188.59,303.53 197.49,303.53 198.12,302.9 200.66,302.9 201.29,303.53 210.19,303.53 210.82,302.9 211.46,302.9 212.72,304.17 217.17,304.17 B23.N2 217.81,304.8 222.25,304.8 222.25,303.53 220.98,302.26 B23.P2 | v407.67,261.62 414.65,261.62 415.29,262.25 422.27,262.25 423.55,260.99 C07.E2 | v255.91,261.62 255.27,262.25 252.73,262.25 249.56,265.43 240.66,265.43 240.03,264.8 237.49,264.8 236.85,265.43 v230.5,265.43
N$66  (via drill 0.61)
  Top 0.254: v155.57,420.37 155.57,395.61 154.31,394.34 A28.F2 | v415.93,420.37 v415.93,252.09
  Bottom 0.254: v155.57,420.37 170.81,420.37 171.45,419.74 173.35,421.64 309.25,421.64 311.15,419.74 312.42,421 415.29,421 v415.93,420.37 | v415.93,252.09 417.19,250.82 420.37,250.82 C07.J2 421,251.46 421.64,251.46 423.55,253.36 C07.H2
N$67  (via drill 0.61)
  Top 0.254: v181.61,300.36 180.97,300.99 180.97,309.25 182.25,310.52 182.25,313.69 B26.K2
  Route3 0.254: v220.98,303.53 220.98,307.34 B23.M2
  Bottom 0.254: v220.98,303.53 213.36,303.53 209.55,299.72 199.39,299.72 198.75,300.36 189.87,300.36 189.23,299.72 186.69,299.72 186.06,300.36 v181.61,300.36
N$68
  Bottom 0.254: F08.M2 411.48,35.56 415.93,35.56 417.19,36.83 417.83,36.83 418.46,36.2 429.26,36.2 429.89,36.83 434.98,36.83 436.25,35.56 F06.M2
N$69  (via drill 0.61)
  Top 0.254: v421.64,249.56 422.27,250.19 422.27,252.09 421,253.36 421,256.54 C07.F2
  Bottom 0.254: v421.64,249.56 417.19,249.56 416.56,248.92 412.12,248.92 411.48,248.28 C08.K2
N$70  (via drill 0.61)
  Top 0.254: 133.35,160.66 132.08,159.38 D30.S2 | 133.35,160.66 v133.35,173.99 | v133.35,123.19 133.35,160.66
  Route2 0.254: v133.35,123.19 134.62,123.19 135.89,121.92 144.78,121.92 144.78,118.11 E29.H2
  Bottom 0.254: v133.35,173.99 131.44,175.89 123.19,175.89 121.92,177.16 119.38,177.16 D31.K2
N$71  (via drill 0.61)
  Top 0.254: v414.02,182.88 415.93,182.88 415.93,177.16 v417.19,175.89 | v431.8,162.56 v431.8,152.4
  Route3 0.254: v395.61,182.88 395.61,186.69 D09.F2 | v448.94,145.41 450.85,143.51 450.85,36.2 v459.11,27.94
  Bottom 0.254: v395.61,182.88 403.86,182.88 404.5,182.25 413.38,182.25 v414.02,182.88 | v417.19,175.89 422.91,175.89 431.17,167.64 431.17,166.37 431.8,165.73 v431.8,162.56 | v431.8,152.4 433.7,150.5 434.98,150.5 438.79,146.69 445.77,146.69 447.04,145.41 v448.94,145.41 | v459.11,27.94 459.74,27.3 467.36,27.3 468,26.67 474.98,26.67 476.25,27.94 476.25,31.12 471.81,31.12 F03.N2
N$72  (via drill 0.61)
  Top 0.254: 425.45,16.51 428.62,16.51 v433.7,21.59 | 425.45,16.51 424.18,16.51 F07.U2 | 425.45,16.51 425.45,67.31 424.81,67.94 424.81,79.38 425.45,80.01 425.45,137.16 424.18,138.43 424.18,148.59 425.45,149.86 425.45,203.84 424.18,205.1 424.18,221.61 C07.U2
  Bottom 0.254: C07.V2 421,219.71 422.91,221.61 423.55,221.61 C07.U2 | v433.7,21.59 435.61,23.49 441.96,23.49 448.31,29.84 454.66,29.84 455.3,30.48 464.19,30.48 464.82,29.84 467.36,29.84 468,30.48 473.07,30.48 474.35,29.21 F03.P2
N$73  (via drill 0.61)
  Top 0.254: v290.19,44.45 292.1,42.55 292.1,22.86 302.89,12.06 302.89,5.71 305.44,3.17 324.49,3.17 v324.49,4.44 | v387.99,7.62 v392.43,12.06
